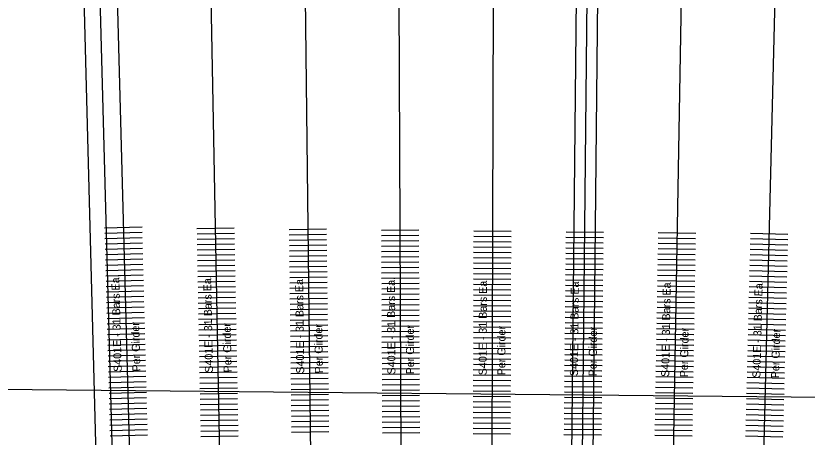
# Model space of a CAD drawing. Extents: x 632276 to 635000, y 381313 to 381846.
# Drawn here: x 634781.2 to 634855.3, y 381486.6 to 381526.1 of the extents above; entities that cross this region are included whole.
import ezdxf

# ---------------------------------------------------------------- set-up
doc = ezdxf.new("R2010")
doc.units = 0
for name, color, linetype in [('B_Boring Annot', 7, 'Continuous'), ('B_No_Plot', 7, 'Continuous'), ('R_Border_Scale', 7, 'Continuous'), ('R_Road Edge of Shoulder', 7, 'Continuous'), ('R_Shade Removal', 7, 'Continuous'), ('R_Wall', 7, 'Continuous')]:
    doc.layers.add(name, color=color, linetype=linetype)

msp = doc.modelspace()

# ---------------------------------------------------------------- linework, layer by layer
at = {"layer": 'B_Boring Annot'}
for p, q in [((634832.38, 381395.621), (634835.411, 381700.486)), ((634834.38, 381395.601), (634837.411, 381700.466)), ((634785.119, 381621.102), (634790.932, 381401.034)), ((634786.619, 381621.142), (634792.431, 381401.073))]:
    msp.add_line(p, q, dxfattribs=at)
at = {"layer": 'B_No_Plot'}
msp.add_line((634670.004, 381492.24), (634998.644, 381488.973), dxfattribs=at)
at = {"layer": 'R_Border_Scale'}
for p, q in [((634793.025, 381506.321), (634789.526, 381506.229)), ((634801.665, 381506.227), (634798.165, 381506.16)), ((634810.304, 381506.131), (634806.805, 381506.089)), ((634818.944, 381506.034), (634815.444, 381506.018)), ((634827.584, 381505.937), (634824.084, 381505.946)), ((634836.228, 381505.838), (634832.729, 381505.874)), ((634793.038, 381505.822), (634789.54, 381505.729)), ((634793.051, 381505.322), (634789.553, 381505.229)), ((634801.674, 381505.727), (634798.175, 381505.66)), ((634801.684, 381505.227), (634798.185, 381505.16)), ((634810.31, 381505.631), (634806.811, 381505.589)), ((634810.316, 381505.131), (634806.817, 381505.089)), ((634818.946, 381505.534), (634815.446, 381505.518)), ((634827.582, 381505.437), (634824.082, 381505.446)), ((634836.223, 381505.338), (634832.724, 381505.374)), ((634844.86, 381505.239), (634841.361, 381505.3)), ((634844.869, 381505.739), (634841.37, 381505.8)), ((634853.496, 381505.14), (634849.997, 381505.226)), ((634853.508, 381505.639), (634850.009, 381505.725)), ((634793.065, 381504.822), (634789.566, 381504.73)), ((634801.693, 381504.727), (634798.194, 381504.66)), ((634810.322, 381504.631), (634806.822, 381504.589)), ((634818.949, 381505.034), (634815.449, 381505.018)), ((634818.951, 381504.534), (634815.451, 381504.518)), ((634827.58, 381504.437), (634824.08, 381504.446)), ((634827.581, 381504.937), (634824.081, 381504.946)), ((634836.213, 381504.338), (634832.713, 381504.374)), ((634836.218, 381504.838), (634832.718, 381504.874)), ((634844.852, 381504.739), (634841.352, 381504.8)), ((634853.484, 381504.64), (634849.985, 381504.726)), ((634793.078, 381504.322), (634789.579, 381504.23)), ((634793.091, 381503.822), (634789.592, 381503.73)), ((634801.703, 381504.227), (634798.204, 381504.16)), ((634801.713, 381503.727), (634798.213, 381503.66)), ((634810.328, 381504.131), (634806.828, 381504.089)), ((634810.334, 381503.631), (634806.834, 381503.589)), ((634818.953, 381504.034), (634815.453, 381504.018)), ((634827.578, 381503.937), (634824.078, 381503.946)), ((634836.208, 381503.838), (634832.708, 381503.874)), ((634844.834, 381503.74), (634841.335, 381503.8)), ((634844.843, 381504.239), (634841.344, 381504.3)), ((634853.459, 381503.64), (634849.96, 381503.726)), ((634853.471, 381504.14), (634849.972, 381504.226)), ((634793.104, 381503.323), (634789.606, 381503.23)), ((634801.722, 381503.227), (634798.223, 381503.16)), ((634810.34, 381503.131), (634806.84, 381503.089)), ((634818.956, 381503.534), (634815.456, 381503.518)), ((634818.958, 381503.034), (634815.458, 381503.018)), ((634827.576, 381502.937), (634824.076, 381502.946)), ((634827.577, 381503.437), (634824.077, 381503.446)), ((634836.203, 381503.338), (634832.703, 381503.374)), ((634844.826, 381503.24), (634841.326, 381503.3)), ((634853.447, 381503.14), (634849.948, 381503.226)), ((634793.117, 381502.823), (634789.619, 381502.73)), ((634793.131, 381502.323), (634789.632, 381502.23)), ((634801.732, 381502.727), (634798.232, 381502.66)), ((634801.741, 381502.227), (634798.242, 381502.16)), ((634810.346, 381502.631), (634806.846, 381502.589)), ((634818.96, 381502.534), (634815.46, 381502.518)), ((634827.574, 381502.437), (634824.074, 381502.446)), ((634836.193, 381502.338), (634832.693, 381502.374)), ((634836.198, 381502.838), (634832.698, 381502.874)), ((634844.808, 381502.24), (634841.309, 381502.3)), ((634844.817, 381502.74), (634841.318, 381502.8)), ((634853.422, 381502.14), (634849.923, 381502.226)), ((634853.435, 381502.64), (634849.936, 381502.726)), ((634793.144, 381501.823), (634789.645, 381501.731)), ((634801.751, 381501.727), (634798.252, 381501.66)), ((634810.352, 381502.131), (634806.852, 381502.089)), ((634810.358, 381501.631), (634806.858, 381501.589)), ((634818.962, 381502.034), (634815.462, 381502.018)), ((634818.965, 381501.534), (634815.465, 381501.518)), ((634827.572, 381501.437), (634824.072, 381501.446)), ((634827.573, 381501.937), (634824.073, 381501.946)), ((634836.188, 381501.838), (634832.688, 381501.874)), ((634844.8, 381501.74), (634841.3, 381501.8)), ((634853.41, 381501.641), (634849.911, 381501.727)), ((634793.157, 381501.323), (634789.658, 381501.231)), ((634793.17, 381500.823), (634789.672, 381500.731)), ((634801.76, 381501.227), (634798.261, 381501.16)), ((634801.77, 381500.728), (634798.271, 381500.661)), ((634810.364, 381501.131), (634806.864, 381501.089)), ((634818.967, 381501.034), (634815.467, 381501.018)), ((634827.57, 381500.937), (634824.07, 381500.946)), ((634836.178, 381500.838), (634832.678, 381500.874)), ((634836.183, 381501.338), (634832.683, 381501.374)), ((634844.783, 381500.74), (634841.283, 381500.801)), ((634844.791, 381501.24), (634841.292, 381501.3)), ((634853.385, 381500.641), (634849.886, 381500.727)), ((634853.398, 381501.141), (634849.899, 381501.227)), ((634793.183, 381500.324), (634789.685, 381500.231)), ((634801.78, 381500.228), (634798.28, 381500.161)), ((634810.37, 381500.631), (634806.87, 381500.59)), ((634810.376, 381500.131), (634806.876, 381500.09)), ((634818.969, 381500.534), (634815.469, 381500.518)), ((634818.972, 381500.034), (634815.472, 381500.018)), ((634827.568, 381499.937), (634824.068, 381499.946)), ((634827.569, 381500.437), (634824.069, 381500.446)), ((634836.173, 381500.338), (634832.673, 381500.374)), ((634844.774, 381500.24), (634841.274, 381500.301)), ((634853.373, 381500.141), (634849.874, 381500.227)), ((634793.197, 381499.824), (634789.698, 381499.731)), ((634793.21, 381499.324), (634789.711, 381499.232)), ((634801.789, 381499.728), (634798.29, 381499.661)), ((634801.799, 381499.228), (634798.299, 381499.161)), ((634810.382, 381499.631), (634806.882, 381499.59)), ((634818.974, 381499.534), (634815.474, 381499.518)), ((634827.566, 381499.437), (634824.066, 381499.446)), ((634836.163, 381499.338), (634832.663, 381499.374)), ((634836.168, 381499.838), (634832.668, 381499.874)), ((634844.757, 381499.24), (634841.257, 381499.301)), ((634844.765, 381499.74), (634841.266, 381499.801)), ((634853.349, 381499.141), (634849.85, 381499.227)), ((634853.361, 381499.641), (634849.862, 381499.727)), ((634793.223, 381498.824), (634789.724, 381498.732)), ((634801.808, 381498.728), (634798.309, 381498.661)), ((634810.388, 381499.131), (634806.888, 381499.09)), ((634810.393, 381498.631), (634806.894, 381498.59)), ((634818.976, 381499.034), (634815.476, 381499.018)), ((634818.979, 381498.534), (634815.479, 381498.518)), ((634827.564, 381498.437), (634824.064, 381498.446)), ((634827.565, 381498.937), (634824.065, 381498.946)), ((634836.158, 381498.838), (634832.658, 381498.874)), ((634844.748, 381498.74), (634841.248, 381498.801)), ((634853.336, 381498.641), (634849.837, 381498.727)), ((634793.236, 381498.324), (634789.738, 381498.232)), ((634793.249, 381497.824), (634789.751, 381497.732)), ((634801.818, 381498.228), (634798.319, 381498.161)), ((634801.827, 381497.728), (634798.328, 381497.661)), ((634810.399, 381498.131), (634806.9, 381498.09)), ((634818.981, 381498.034), (634815.481, 381498.018)), ((634827.562, 381497.937), (634824.062, 381497.946)), ((634836.148, 381497.839), (634832.648, 381497.874)), ((634836.153, 381498.338), (634832.653, 381498.374)), ((634844.731, 381497.74), (634841.231, 381497.801)), ((634844.739, 381498.24), (634841.24, 381498.301)), ((634853.312, 381497.642), (634849.813, 381497.728)), ((634853.324, 381498.142), (634849.825, 381498.228)), ((634793.263, 381497.325), (634789.764, 381497.232)), ((634801.837, 381497.228), (634798.338, 381497.161)), ((634810.405, 381497.631), (634806.906, 381497.59)), ((634810.411, 381497.131), (634806.912, 381497.09)), ((634818.983, 381497.534), (634815.483, 381497.518)), ((634818.986, 381497.034), (634815.486, 381497.018)), ((634827.561, 381497.437), (634824.061, 381497.446)), ((634836.142, 381497.339), (634832.643, 381497.374)), ((634844.722, 381497.24), (634841.222, 381497.301)), ((634853.299, 381497.142), (634849.8, 381497.228)), ((634793.276, 381496.825), (634789.777, 381496.732)), ((634793.289, 381496.325), (634789.79, 381496.233)), ((634801.847, 381496.728), (634798.347, 381496.661)), ((634801.856, 381496.228), (634798.357, 381496.161)), ((634810.417, 381496.631), (634806.918, 381496.59)), ((634818.988, 381496.534), (634815.488, 381496.518)), ((634827.558, 381496.437), (634824.058, 381496.446)), ((634827.56, 381496.937), (634824.06, 381496.946)), ((634836.132, 381496.339), (634832.633, 381496.374)), ((634836.137, 381496.839), (634832.638, 381496.874)), ((634844.705, 381496.241), (634841.205, 381496.301)), ((634844.713, 381496.741), (634841.214, 381496.801)), ((634853.275, 381496.142), (634849.776, 381496.228)), ((634853.287, 381496.642), (634849.788, 381496.728)), ((634793.302, 381495.825), (634789.803, 381495.733)), ((634801.866, 381495.728), (634798.366, 381495.661)), ((634810.423, 381496.131), (634806.923, 381496.09)), ((634810.429, 381495.631), (634806.929, 381495.59)), ((634818.99, 381496.034), (634815.49, 381496.018)), ((634818.992, 381495.534), (634815.492, 381495.518)), ((634827.557, 381495.937), (634824.057, 381495.946)), ((634836.127, 381495.839), (634832.627, 381495.874)), ((634844.696, 381495.741), (634841.197, 381495.801)), ((634853.263, 381495.642), (634849.764, 381495.728)), ((634793.315, 381495.325), (634789.817, 381495.233)), ((634793.329, 381494.825), (634789.83, 381494.733)), ((634801.875, 381495.229), (634798.376, 381495.162)), ((634810.435, 381495.131), (634806.935, 381495.09)), ((634818.995, 381495.034), (634815.495, 381495.018)), ((634827.554, 381494.937), (634824.054, 381494.946)), ((634827.556, 381495.437), (634824.056, 381495.446)), ((634836.117, 381494.839), (634832.617, 381494.874)), ((634836.122, 381495.339), (634832.622, 381495.374)), ((634844.679, 381494.741), (634841.179, 381494.801)), ((634844.687, 381495.241), (634841.188, 381495.301)), ((634853.25, 381495.143), (634849.751, 381495.229)), ((634793.342, 381494.326), (634789.843, 381494.233)), ((634801.885, 381494.729), (634798.386, 381494.662)), ((634801.894, 381494.229), (634798.395, 381494.162)), ((634810.441, 381494.632), (634806.941, 381494.59)), ((634810.447, 381494.132), (634806.947, 381494.09)), ((634818.997, 381494.534), (634815.497, 381494.518)), ((634818.999, 381494.034), (634815.499, 381494.018)), ((634827.553, 381494.437), (634824.053, 381494.446)), ((634836.112, 381494.339), (634832.612, 381494.374)), ((634844.67, 381494.241), (634841.171, 381494.301)), ((634853.226, 381494.143), (634849.727, 381494.229)), ((634853.238, 381494.643), (634849.739, 381494.729)), ((634793.355, 381493.826), (634789.856, 381493.733)), ((634793.368, 381493.326), (634789.869, 381493.234)), ((634801.904, 381493.729), (634798.405, 381493.662)), ((634810.453, 381493.632), (634806.953, 381493.59)), ((634819.002, 381493.534), (634815.502, 381493.518)), ((634827.55, 381493.437), (634824.05, 381493.446)), ((634827.552, 381493.937), (634824.052, 381493.946)), ((634836.102, 381493.339), (634832.602, 381493.374)), ((634836.107, 381493.839), (634832.607, 381493.874)), ((634844.653, 381493.241), (634841.153, 381493.302)), ((634844.661, 381493.741), (634841.162, 381493.802)), ((634853.213, 381493.643), (634849.714, 381493.729)), ((634793.381, 381492.826), (634789.883, 381492.734)), ((634801.914, 381493.229), (634798.414, 381493.162)), ((634801.923, 381492.729), (634798.424, 381492.662)), ((634810.459, 381493.132), (634806.959, 381493.09)), ((634810.465, 381492.632), (634806.965, 381492.59)), ((634819.004, 381493.034), (634815.504, 381493.018)), ((634819.006, 381492.534), (634815.506, 381492.518)), ((634827.549, 381492.937), (634824.049, 381492.946)), ((634836.097, 381492.839), (634832.597, 381492.874)), ((634844.644, 381492.741), (634841.145, 381492.802)), ((634853.189, 381492.643), (634849.69, 381492.729)), ((634853.201, 381493.143), (634849.702, 381493.229)), ((634793.395, 381492.326), (634789.896, 381492.234)), ((634793.408, 381491.827), (634789.909, 381491.734)), ((634801.933, 381492.229), (634798.433, 381492.162)), ((634810.471, 381492.132), (634806.971, 381492.09)), ((634819.009, 381492.034), (634815.509, 381492.018)), ((634827.546, 381491.937), (634824.046, 381491.946)), ((634827.548, 381492.437), (634824.048, 381492.446)), ((634836.087, 381491.839), (634832.587, 381491.874)), ((634836.092, 381492.339), (634832.592, 381492.374)), ((634844.627, 381491.741), (634841.127, 381491.802)), ((634844.635, 381492.241), (634841.136, 381492.302)), ((634853.177, 381492.143), (634849.678, 381492.229)), ((634793.421, 381491.327), (634789.922, 381491.234)), ((634801.942, 381491.729), (634798.443, 381491.662)), ((634801.952, 381491.229), (634798.453, 381491.162)), ((634810.477, 381491.632), (634806.977, 381491.59)), ((634810.483, 381491.132), (634806.983, 381491.09)), ((634819.011, 381491.534), (634815.511, 381491.518)), ((634819.013, 381491.034), (634815.513, 381491.018)), ((634827.545, 381491.437), (634824.045, 381491.446)), ((634836.082, 381491.339), (634832.582, 381491.374)), ((634844.618, 381491.241), (634841.119, 381491.302)), ((634853.152, 381491.144), (634849.653, 381491.23)), ((634853.164, 381491.644), (634849.665, 381491.73)), ((634793.434, 381490.827), (634789.935, 381490.734)), ((634793.447, 381490.327), (634789.949, 381490.235)), ((634801.961, 381490.729), (634798.462, 381490.662)), ((634810.489, 381490.632), (634806.989, 381490.59)), ((634819.016, 381490.534), (634815.516, 381490.518)), ((634827.542, 381490.437), (634824.042, 381490.446)), ((634827.544, 381490.937), (634824.044, 381490.946)), ((634836.074, 381490.339), (634832.575, 381490.374)), ((634836.077, 381490.839), (634832.577, 381490.874)), ((634844.602, 381490.242), (634841.103, 381490.302)), ((634844.609, 381490.741), (634841.11, 381490.802)), ((634853.14, 381490.644), (634849.641, 381490.73)), ((634793.461, 381489.827), (634789.962, 381489.735)), ((634801.971, 381490.229), (634798.472, 381490.162)), ((634801.981, 381489.73), (634798.481, 381489.663)), ((634810.494, 381490.132), (634806.995, 381490.09)), ((634810.5, 381489.632), (634807.001, 381489.59)), ((634819.018, 381490.034), (634815.518, 381490.018)), ((634827.541, 381489.937), (634824.041, 381489.946)), ((634836.069, 381489.839), (634832.569, 381489.874)), ((634844.593, 381489.742), (634841.094, 381489.802)), ((634853.116, 381489.644), (634849.617, 381489.73)), ((634853.129, 381490.144), (634849.63, 381490.23)), ((634793.474, 381489.327), (634789.975, 381489.235)), ((634793.487, 381488.828), (634789.988, 381488.735)), ((634801.99, 381489.23), (634798.491, 381489.163)), ((634810.506, 381489.132), (634807.007, 381489.09)), ((634819.02, 381489.534), (634815.52, 381489.518)), ((634819.022, 381489.034), (634815.522, 381489.018)), ((634827.538, 381488.937), (634824.038, 381488.946)), ((634827.54, 381489.437), (634824.04, 381489.446)), ((634836.059, 381488.839), (634832.559, 381488.874)), ((634836.064, 381489.339), (634832.564, 381489.374)), ((634844.585, 381489.242), (634841.085, 381489.302)), ((634853.104, 381489.144), (634849.605, 381489.23)), ((634793.5, 381488.328), (634790.001, 381488.235)), ((634802, 381488.73), (634798.5, 381488.663)), ((634802.009, 381488.23), (634798.51, 381488.163)), ((634810.512, 381488.632), (634807.013, 381488.59)), ((634810.518, 381488.132), (634807.018, 381488.09)), ((634819.025, 381488.534), (634815.525, 381488.518)), ((634827.537, 381488.437), (634824.037, 381488.446)), ((634836.054, 381488.339), (634832.554, 381488.374)), ((634844.567, 381488.242), (634841.068, 381488.302)), ((634844.576, 381488.742), (634841.077, 381488.802)), ((634853.079, 381488.145), (634849.581, 381488.231)), ((634853.092, 381488.644), (634849.593, 381488.73)), ((634793.513, 381487.828), (634790.015, 381487.736)), ((634793.527, 381487.328), (634790.028, 381487.236)), ((634802.019, 381487.73), (634798.52, 381487.663)), ((634810.524, 381487.632), (634807.024, 381487.59)), ((634819.027, 381488.034), (634815.527, 381488.018)), ((634819.029, 381487.534), (634815.529, 381487.518)), ((634827.534, 381487.437), (634824.034, 381487.446)), ((634827.536, 381487.937), (634824.036, 381487.946)), ((634836.044, 381487.339), (634832.544, 381487.374)), ((634836.049, 381487.839), (634832.549, 381487.874)), ((634844.559, 381487.742), (634841.059, 381487.802)), ((634853.067, 381487.645), (634849.568, 381487.731)), ((634793.54, 381486.828), (634790.041, 381486.736)), ((634802.028, 381487.23), (634798.529, 381487.163)), ((634802.038, 381486.73), (634798.539, 381486.663)), ((634810.53, 381487.132), (634807.03, 381487.09)), ((634819.032, 381487.034), (634815.532, 381487.018)), ((634827.533, 381486.937), (634824.033, 381486.946)), ((634836.039, 381486.839), (634832.539, 381486.874)), ((634844.541, 381486.742), (634841.042, 381486.803)), ((634844.55, 381487.242), (634841.051, 381487.303)), ((634853.043, 381486.645), (634849.544, 381486.731)), ((634853.055, 381487.145), (634849.556, 381487.231))]:
    msp.add_line(p, q, dxfattribs=at)
at = {"layer": 'R_Road Edge of Shoulder'}
msp.add_line((634833.143, 381371.836), (634836.411, 381700.476), dxfattribs=at)
at = {"layer": 'R_Shade Removal'}
for p, q in [((634788.244, 381621.071), (634794.056, 381401.003)), ((634801.93, 381400.924), (634797.718, 381620.977)), ((634807.191, 381620.883), (634809.805, 381400.846)), ((634817.68, 381400.768), (634816.665, 381620.789)), ((634826.138, 381620.694), (634825.554, 381400.689)), ((634845.095, 381620.506), (634841.305, 381400.533)), ((634849.179, 381400.454), (634854.569, 381620.412))]:
    msp.add_line(p, q, dxfattribs=at)

# ---------------------------------------------------------------- texts
at = {"layer": 'R_Wall'}
for s, rotation, p in [('S401E - 31 Bars Ea,', 91.52278, (634791.132, 381492.767)), ('S401E - 31 Bars Ea,', 91.10681, (634799.674, 381492.686)), ('S401E - 31 Bars Ea,', 90.69065, (634808.215, 381492.605)), ('S401E - 31 Bars Ea,', 90.27437, (634816.756, 381492.524)), ('S401E - 31 Bars Ea,', 89.85799, (634825.298, 381492.443)), ('S401E - 31 Bars Ea,', 89.43036, (634833.842, 381492.361)), ('S401E - 31 Bars Ea,', 89.01848, (634842.386, 381492.28)), ('S401E - 31 Bars Ea,', 88.60208, (634850.927, 381492.199)), ('Per Girder', 91.52278, (634792.882, 381492.813)), ('Per Girder', 91.10681, (634801.423, 381492.72)), ('Per Girder', 90.69065, (634809.965, 381492.626)), ('Per Girder', 90.27437, (634818.506, 381492.532)), ('Per Girder', 89.85799, (634827.048, 381492.438)), ('Per Girder', 89.43036, (634835.592, 381492.344)), ('Per Girder', 89.01848, (634844.136, 381492.25)), ('Per Girder', 88.60208, (634852.677, 381492.156))]:
    msp.add_text(s, height=0.75, rotation=rotation, dxfattribs=at).set_placement(p)

doc.saveas('drawing.dxf')
